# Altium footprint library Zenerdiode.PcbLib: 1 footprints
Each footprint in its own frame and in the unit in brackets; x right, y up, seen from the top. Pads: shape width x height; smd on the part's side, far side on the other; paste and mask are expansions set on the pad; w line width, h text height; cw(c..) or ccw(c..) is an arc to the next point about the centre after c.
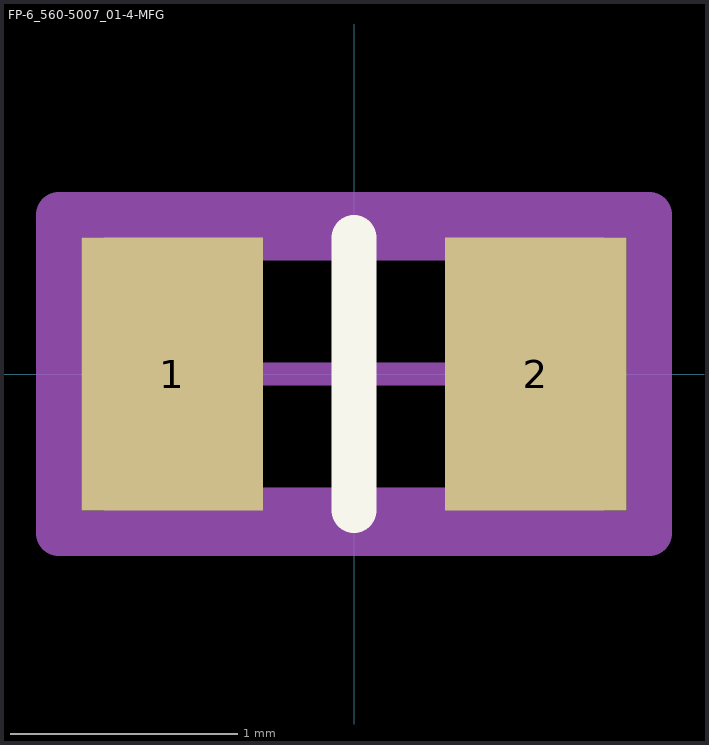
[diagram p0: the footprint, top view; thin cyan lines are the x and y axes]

## FP-6_560-5007_01-4-MFG [mm]
pads (2):
  rect 0.8x1.2 smd paste+0 mask+0: 1(-0.8,0) 2(0.8,0)
Top Overlay:
  lines w0.2: 0,-0.6 0,0.6
Top Assembly:
  lines w0.2: -1.3,-0.7 -1.3,0.7 1.3,0.7 1.3,-0.7 -1.3,-0.7
  text ".Designator" at 0,-0.001 h1
Top 3D Body:
  lines w0.2: -1,-0.6 -1,0.6 1,0.6 1,-0.6 -1,-0.6
Top Courtyard:
  lines w0.2: -1.3,-0.7 -1.3,0.7 1.3,0.7 1.3,-0.7 -1.3,-0.7
Top Component Center:
  lines w0.1: -0.5,0 0.5,0 ; 0,-0.5 0,0.5
3D body "Diode_Vishay_BZM55B5V1-TR_eec.STEP": height 0.25, standoff 0, extent -1.3,-0.7 1.3,0.7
